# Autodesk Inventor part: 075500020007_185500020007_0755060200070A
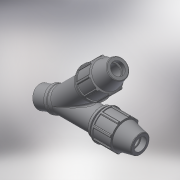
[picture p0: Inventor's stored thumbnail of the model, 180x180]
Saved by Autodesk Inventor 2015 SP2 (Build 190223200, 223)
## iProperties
Created: 2017-02
Part Number: 075500020007_185500020007_0755060200070A
Material: Generic
Description: PLASSON Y FITTING 20-20-3/4"
Document SubType Name: Modeling
Designer: KIM
Mass: 111.65 g
Surface Area: 364.865 cm^2
Volume: 111.65 cm^3
Density: 1 g/cm^3
Appearance: Default
Author: KIM
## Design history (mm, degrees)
derived "07550.ipt"
feature "Solid1::07550.ipt"
tag "TaggingFeature1"
body "Solid1"
other parameters: "d4" = 9.5, "d5" = 22.8, "d7" = 48, "d11" = 3.8, "d13" = 120 deg, "d15" = 12 deg, "d16" = 41.76, "d18" = 1, "d19" = 35 deg, "d20" = 17.5 deg, "d21" = 44.64, "d23" = 0, "d25" = 360 deg, "d27" = 0.96, "d33" = 0.4, "d42" = 28.5, "d43" = 1.44, "d46" = 0.6, "d51" = 114, "d68" = 3.8, "d91" = 36, "d93" = 57, "d95" = 18.5087, "d98" = 2.4, "d99" = 0, "d101" = 45 deg, "d103" = 2.4, "d104" = 160 deg, "d105" = 26.441, "d106" = 30.40715, "d107" = 18, "d108" = 27, "d109" = 18.5087, "d110" = 36, "d111" = 8.1, "d113" = 0.52882, "d116" = 0.96, "E_" = 48, "A_" = 114, "l_" = 57, "l_2" = 18, "R_" = 26.441
